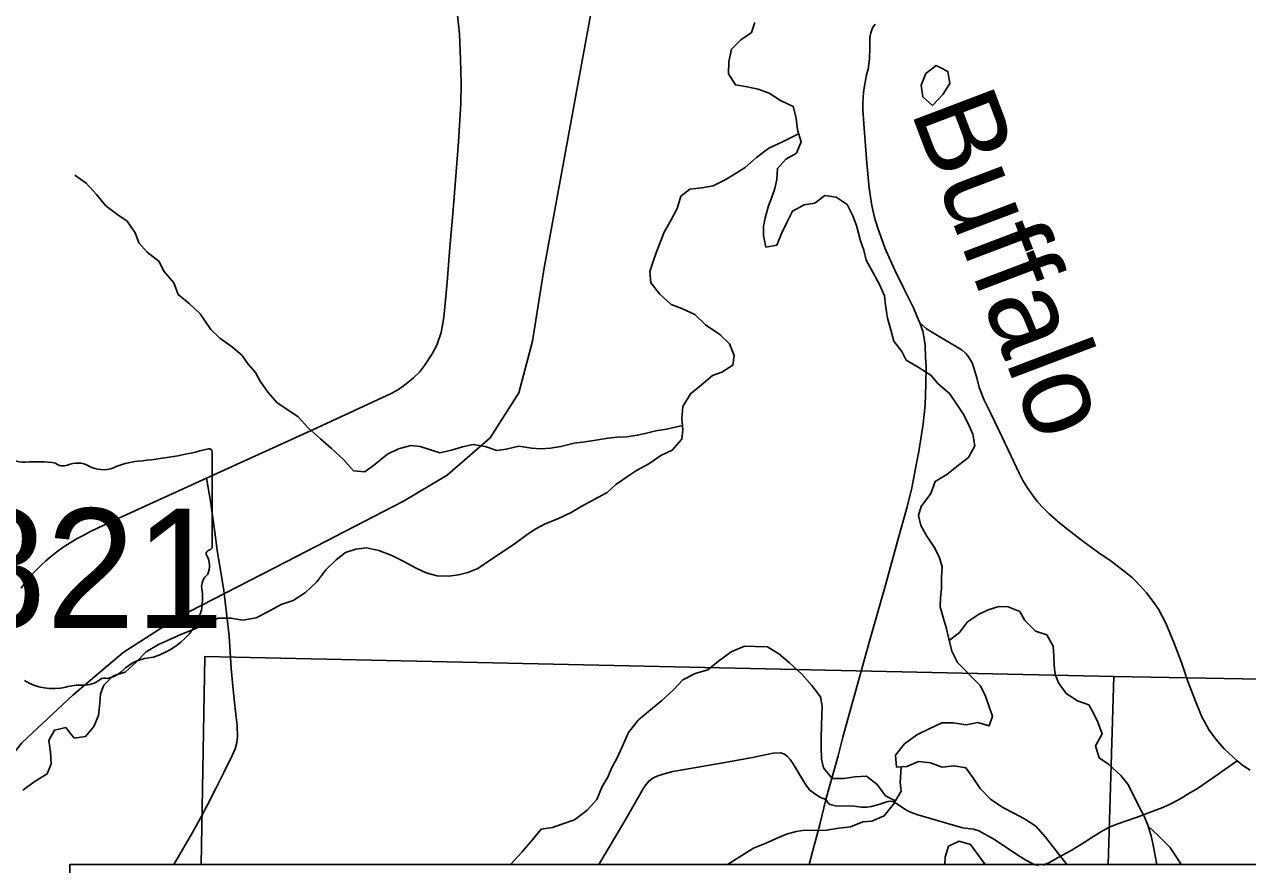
# Model space of a CAD drawing. Extents: x 0 to 34, y 0 to 22.
# Drawn here: x 5.615 to 6.964, y 18.86 to 19.787 of the extents above; entities that cross this region are included whole.
import ezdxf

# ---------------------------------------------------------------- set-up
doc = ezdxf.new("R2010")
doc.units = 0
for name, color, linetype in [('GM_X_Corporation', 7, 'Continuous'), ('GM_X_County_Road', 7, 'Continuous'), ('GM_X_Minor_Lake', 7, 'Continuous'), ('GM_X_Minor_River', 7, 'Continuous'), ('GM_X_Minor_River_Text', 7, 'Continuous'), ('GM_X_Rail_Line', 7, 'Continuous'), ('GM_X_State_Location', 7, 'Continuous'), ('GM_X_State_Route', 7, 'Continuous'), ('GM_X_State_Shield', 7, 'Continuous'), ('GM_X_Township_Road', 7, 'Continuous'), ('SH_Data', 7, 'Continuous')]:
    doc.layers.add(name, color=color, linetype=linetype)

msp = doc.modelspace()

# ---------------------------------------------------------------- linework, layer by layer
at = {"layer": 'GM_X_Corporation'}
for points in [[(5.8098, 18.8602), (5.814, 19.0894), (6.8161, 19.0676), (6.8097, 18.8602)], [(6.8097, 18.8602), (6.8161, 19.0676), (7.8304, 19.049), (7.8278, 18.8602)]]:
    msp.add_lwpolyline(points, dxfattribs=at)
at = {"layer": 'GM_X_County_Road'}
for points in [[(6.6022, 19.4574), (6.6096, 19.4508), (6.6197, 19.4445), (6.6333, 19.4366), (6.6416, 19.4317), (6.6487, 19.4273), (6.6525, 19.4242), (6.655, 19.4212), (6.6599, 19.4133), (6.6619, 19.408), (6.6651, 19.3969), (6.6676, 19.3864), (6.6731, 19.3724), (6.6806, 19.3576), (6.6933, 19.3307), (6.7057, 19.3043), (6.7116, 19.2917), (6.7157, 19.2835), (6.7206, 19.276), (6.7267, 19.2672), (6.7321, 19.2601), (6.7384, 19.2533), (6.7449, 19.2468), (6.7569, 19.2364), (6.7685, 19.227), (6.7834, 19.2155), (6.8023, 19.2022), (6.8118, 19.1957), (6.8214, 19.1885), (6.8293, 19.1822), (6.8366, 19.1762), (6.8456, 19.1673), (6.8522, 19.1597), (6.8591, 19.1505), (6.8654, 19.1416), (6.8734, 19.1263), (6.8824, 19.1049), (6.8908, 19.083), (6.8974, 19.0631), (6.906, 19.0402), (6.9131, 19.0231), (6.9212, 19.0084), (6.9287, 18.9984), (6.9376, 18.9878), (6.9521, 18.9744), (6.9585, 18.9695), (6.9663, 18.9641)], [(5.7797, 18.8602), (5.8004, 18.8954), (5.8098, 18.9127), (5.8168, 18.9259), (5.8263, 18.9448), (5.8343, 18.9611), (5.8442, 18.9805), (5.8475, 18.9878), (5.849, 18.9948), (5.85, 19.0009), (5.8495, 19.0136), (5.8473, 19.0323), (5.8453, 19.0532), (5.8431, 19.0765), (5.8407, 19.1122), (5.8347, 19.1624), (5.8276, 19.2069), (5.8248, 19.2267), (5.82, 19.2607), (5.8159, 19.2861)]]:
    msp.add_lwpolyline(points, dxfattribs=at)
at = {"layer": 'GM_X_Minor_Lake'}
for points in [[(6.6252, 19.7387), (6.6201, 19.7413), (6.6087, 19.7326), (6.6038, 19.7197), (6.6056, 19.7068), (6.6162, 19.6973)], [(6.6162, 19.6973), (6.6276, 19.7094), (6.6352, 19.7215), (6.6329, 19.7348), (6.6252, 19.7387)]]:
    msp.add_lwpolyline(points, dxfattribs=at)
at = {"layer": 'GM_X_Minor_River'}
for points in [[(6.4201, 19.7889), (6.4167, 19.7776), (6.405, 19.7696), (6.3947, 19.7594), (6.3917, 19.7457), (6.3913, 19.7321), (6.3988, 19.72), (6.4117, 19.7177), (6.4241, 19.7154), (6.4362, 19.7108), (6.4487, 19.7028), (6.4627, 19.696), (6.4657, 19.6831), (6.4672, 19.6702), (6.4713, 19.6573), (6.4664, 19.6448), (6.4546, 19.638), (6.4452, 19.6278), (6.4444, 19.6157), (6.4425, 19.6058), (6.439, 19.596), (6.4352, 19.5865), (6.4318, 19.5732), (6.4299, 19.5638), (6.4299, 19.5539), (6.4325, 19.541), (6.4446, 19.5433), (6.4496, 19.5562), (6.4556, 19.5683), (6.4617, 19.5808), (6.4746, 19.5876), (6.4863, 19.5895), (6.4973, 19.5978), (6.5098, 19.5962), (6.5222, 19.5879), (6.5282, 19.5754), (6.5324, 19.5648), (6.5369, 19.5481), (6.5403, 19.5378), (6.5429, 19.5268), (6.5508, 19.5128), (6.5576, 19.4999), (6.5632, 19.4874), (6.5644, 19.4772), (6.5666, 19.4628), (6.5704, 19.4499), (6.5737, 19.4373), (6.5824, 19.426), (6.5873, 19.4165), (6.6005, 19.4085), (6.6145, 19.3998), (6.6224, 19.3903), (6.6349, 19.3796), (6.6428, 19.3683), (6.6507, 19.3561), (6.6564, 19.3447), (6.6605, 19.3349), (6.6628, 19.322), (6.6559, 19.3091), (6.6449, 19.3004), (6.6321, 19.2902), (6.6192, 19.2826), (6.6143, 19.2694), (6.6036, 19.255), (6.6006, 19.2451), (6.6032, 19.2341), (6.61, 19.2224), (6.6187, 19.2091), (6.624, 19.1985), (6.627, 19.1886), (6.6262, 19.1773), (6.6262, 19.1644), (6.625, 19.1541), (6.6246, 19.1443)], [(6.4685, 19.666), (6.4501, 19.6566), (6.4357, 19.6502), (6.4221, 19.64), (6.4096, 19.629), (6.3998, 19.6226), (6.3876, 19.6154), (6.3744, 19.6086), (6.3619, 19.6063), (6.3487, 19.6048), (6.3388, 19.5972), (6.3346, 19.5836), (6.3282, 19.5711), (6.3202, 19.5575), (6.3168, 19.548), (6.3119, 19.5359), (6.3081, 19.5253), (6.3046, 19.5143), (6.3058, 19.5018), (6.3156, 19.4892), (6.328, 19.4779), (6.3397, 19.4733), (6.3541, 19.4668), (6.3658, 19.4554), (6.3817, 19.4448), (6.3922, 19.4342), (6.3975, 19.4217), (6.396, 19.4107), (6.3838, 19.4031), (6.3736, 19.3993), (6.3615, 19.3891), (6.3494, 19.3793), (6.341, 19.3653), (6.3399, 19.352), (6.341, 19.3395), (6.3398, 19.3293), (6.3292, 19.3171), (6.3167, 19.3111), (6.3035, 19.302), (6.2899, 19.2948), (6.28, 19.288), (6.2671, 19.2793), (6.2573, 19.2706), (6.2433, 19.2627), (6.2297, 19.2555), (6.2179, 19.2483), (6.2032, 19.2415), (6.1892, 19.2358), (6.1789, 19.2305), (6.1691, 19.2241), (6.1551, 19.2135), (6.129, 19.1961), (6.1149, 19.1866), (6.104, 19.1821), (6.0934, 19.1795), (6.0828, 19.178), (6.0699, 19.1784), (6.0578, 19.1818), (6.0469, 19.1871), (6.0333, 19.1943), (6.0201, 19.2008), (6.0057, 19.2065), (5.9921, 19.2095), (5.9804, 19.208), (5.969, 19.2043), (5.9588, 19.1963), (5.9474, 19.1853), (5.9372, 19.1721), (5.9247, 19.16), (5.9114, 19.1513), (5.8982, 19.1471), (5.8834, 19.1388), (5.8706, 19.1324), (5.8558, 19.1297), (5.8426, 19.132), (5.8286, 19.132), (5.8157, 19.126), (5.8021, 19.1196), (5.7881, 19.1143), (5.776, 19.1086), (5.7627, 19.1029), (5.7491, 19.0946), (5.7381, 19.0833), (5.726, 19.0723), (5.7128, 19.0681), (5.7025, 19.0579), (5.6987, 19.0484), (5.698, 19.0382), (5.6968, 19.0245), (5.6915, 19.0124), (5.6824, 19.0014), (5.6699, 18.9996), (5.6605, 19.0113), (5.648, 19.0083), (5.6419, 18.9969), (5.6438, 18.9841), (5.6445, 18.9712), (5.64, 18.9602), (5.6267, 18.9522), (5.6134, 18.942)], [(6.3406, 19.3442), (6.3228, 19.3403), (6.3111, 19.3384), (6.3009, 19.3357), (6.2907, 19.3335), (6.2793, 19.332), (6.2691, 19.3316), (6.2585, 19.3305), (6.2449, 19.3282), (6.2332, 19.3264), (6.2211, 19.3249), (6.2063, 19.3211), (6.195, 19.3192), (6.1848, 19.3185), (6.1742, 19.3192), (6.1602, 19.3215), (6.1462, 19.3181), (6.136, 19.3166), (6.1231, 19.3212), (6.1099, 19.3235), (6.0978, 19.3208), (6.0857, 19.3171), (6.0728, 19.3141), (6.0513, 19.3213), (6.0411, 19.3221), (6.0275, 19.3187), (6.0154, 19.3126), (6.0017, 19.3016), (5.9904, 19.2933), (5.9779, 19.2945), (5.9669, 19.307), (5.9537, 19.3191), (5.9413, 19.3298), (5.9281, 19.3415), (5.9167, 19.3537), (5.9065, 19.3609), (5.8937, 19.3692), (5.8835, 19.381), (5.8748, 19.3931), (5.8696, 19.4026), (5.8616, 19.4121), (5.8549, 19.4216), (5.8443, 19.4307), (5.8303, 19.4406), (5.8205, 19.4501), (5.8088, 19.4675), (5.7967, 19.4789), (5.7846, 19.4888), (5.7798, 19.5017), (5.7688, 19.5146), (5.7635, 19.5252), (5.7503, 19.5354), (5.7413, 19.5457), (5.7371, 19.5567), (5.7281, 19.5696), (5.7179, 19.5768), (5.7047, 19.5867), (5.6945, 19.5992), (5.6832, 19.6117), (5.6707, 19.6204)], [(6.6246, 19.1443), (6.6284, 19.1314), (6.6314, 19.1215), (6.634, 19.109), (6.6374, 19.0954), (6.6438, 19.0828), (6.6691, 19.0574), (6.6747, 19.0457), (6.6788, 19.0339), (6.6822, 19.0237), (6.6788, 19.0131), (6.666, 19.0169), (6.6531, 19.0142), (6.6391, 19.0165), (6.6266, 19.0165), (6.6126, 19.0097), (6.599, 19.0033), (6.5854, 18.9931), (6.5755, 18.9806), (6.5766, 18.9677), (6.588, 18.9681), (6.6008, 18.9737), (6.6141, 18.9722), (6.6269, 18.9676), (6.6402, 18.9691), (6.653, 18.9668), (6.6605, 18.9562), (6.6688, 18.9441), (6.6802, 18.9323), (6.6938, 18.9232), (6.7059, 18.9167), (6.7176, 18.9107), (6.73, 18.9023), (6.7406, 18.8905), (6.7642, 18.8602)], [(6.6344, 19.1072), (6.6461, 19.1162), (6.6548, 19.1279), (6.6669, 19.1359), (6.6775, 19.1412), (6.6893, 19.1449), (6.6995, 19.1442), (6.7123, 19.1392), (6.718, 19.1294), (6.7297, 19.1176), (6.7421, 19.1134), (6.7493, 19.1009), (6.75, 19.0899), (6.7504, 19.0797), (6.7515, 19.0702), (6.7549, 19.0607), (6.7636, 19.0486), (6.776, 19.0406), (6.7885, 19.0364), (6.7942, 19.0265), (6.7983, 19.0171), (6.8032, 19.0042), (6.796, 18.9909), (6.8001, 18.978), (6.8103, 18.9708), (6.8239, 18.9583), (6.8315, 18.9488), (6.839, 18.9344), (6.8439, 18.9238), (6.8492, 18.9143), (6.8533, 18.9048), (6.8571, 18.8919), (6.8593, 18.8817), (6.8636, 18.8602)], [(6.5752, 18.9304), (6.5645, 18.9359), (6.555, 18.9484), (6.5433, 18.9575), (6.5305, 18.9568), (6.5187, 18.9549), (6.5055, 18.9549), (6.4961, 18.9667), (6.4938, 18.9762), (6.4935, 18.9898), (6.4935, 19), (6.4939, 19.0126), (6.4943, 19.0254), (6.4947, 19.0349), (6.4928, 19.0451), (6.483, 19.0577), (6.4721, 19.0702), (6.4585, 19.0827), (6.4468, 19.0926), (6.4343, 19.1002), (6.4207, 19.1006), (6.409, 19.101), (6.3942, 19.0949), (6.3802, 19.0843), (6.3685, 19.0749), (6.3545, 19.0707), (6.3408, 19.0639), (6.331, 19.0533), (6.3177, 19.0412), (6.3052, 19.0306), (6.2916, 19.0193), (6.281, 19.0056), (6.2741, 18.9901), (6.2684, 18.978), (6.2624, 18.9666), (6.2582, 18.9564), (6.2521, 18.9462), (6.2461, 18.9318), (6.2354, 18.92), (6.2214, 18.9094), (6.2074, 18.9045), (6.1972, 18.9011), (6.1847, 18.8992), (6.1749, 18.8871), (6.1635, 18.8739), (6.1508, 18.8602)], [(6.5818, 18.9679), (6.5804, 18.9506), (6.5815, 18.9412), (6.5731, 18.9268), (6.5629, 18.9139), (6.5493, 18.9079), (6.5394, 18.9071), (6.5258, 18.9018), (6.513, 18.9003), (6.4993, 18.8981), (6.4854, 18.8977), (6.4755, 18.8981), (6.4657, 18.8966), (6.4551, 18.8936), (6.4422, 18.8883), (6.4316, 18.8834), (6.4188, 18.8781), (6.3902, 18.8602)], [(6.8539, 18.9026), (6.8654, 18.8919), (6.8778, 18.8794), (6.8861, 18.8672), (6.8902, 18.8602)], [(6.6743, 18.8602), (6.6581, 18.8823), (6.6457, 18.8861), (6.6339, 18.8805), (6.6301, 18.8683), (6.6298, 18.8602)]]:
    msp.add_lwpolyline(points, dxfattribs=at)
at = {"layer": 'GM_X_Rail_Line'}
msp.add_lwpolyline([(5.1451, 18.1171), (5.1789, 18.1962), (5.2191, 18.2747), (5.3419, 18.505), (5.4365, 18.6966), (5.5699, 18.941), (5.612, 18.9944), (5.6684, 19.0468), (5.7239, 19.094), (5.7833, 19.1322), (5.9037, 19.1938), (6.0328, 19.261), (6.0812, 19.2894), (6.1283, 19.3307), (6.1601, 19.3803), (6.1751, 19.4374), (6.1878, 19.5161), (6.2911, 20.0794)], dxfattribs=at)
at = {"layer": 'GM_X_State_Route'}
for points in [[(5.6113, 19.1649), (5.6154, 19.1703), (5.6218, 19.178), (5.6279, 19.1848), (5.6337, 19.1906), (5.6385, 19.195), (5.6435, 19.1993), (5.6506, 19.2049), (5.6576, 19.2101), (5.6733, 19.2196), (5.6804, 19.2234), (5.6871, 19.227), (5.7108, 19.2384), (5.8159, 19.2861), (5.9385, 19.3422), (6.0193, 19.3795), (6.0275, 19.384), (6.036, 19.3903), (6.044, 19.3968), (6.0505, 19.4033), (6.056, 19.4106), (6.0645, 19.4235), (6.0695, 19.433), (6.0745, 19.4467), (6.0773, 19.4634), (6.0812, 19.5023), (6.0841, 19.5407), (6.0872, 19.5779), (6.0906, 19.6191), (6.0934, 19.6571), (6.0962, 19.6994), (6.0966, 19.7215), (6.0959, 19.748), (6.0945, 19.7761), (6.092, 19.8004)], [(6.5528, 19.7868), (6.5501, 19.7827), (6.548, 19.7775), (6.5471, 19.7724), (6.5471, 19.7613), (6.5468, 19.7488), (6.5451, 19.7373), (6.5435, 19.7309), (6.5411, 19.7189), (6.5402, 19.7115), (6.5392, 19.6997), (6.5394, 19.6931), (6.5405, 19.677), (6.5436, 19.6338), (6.5463, 19.606), (6.5493, 19.5871), (6.5523, 19.5737), (6.5555, 19.5631), (6.5635, 19.5401), (6.5748, 19.5155), (6.5843, 19.4962), (6.5951, 19.474), (6.5994, 19.4642), (6.6022, 19.4574), (6.6054, 19.4484), (6.6066, 19.4426), (6.6079, 19.4324), (6.6085, 19.4195), (6.609, 19.4091), (6.6088, 19.3898), (6.6081, 19.3669), (6.606, 19.3462), (6.6014, 19.3179), (6.601, 19.3158)], [(6.601, 19.3158), (6.5988, 19.3046), (6.5933, 19.2757), (6.5882, 19.2547), (6.5784, 19.2193), (6.5643, 19.1682), (6.5466, 19.1066), (6.5301, 19.0471), (6.5239, 19.0244), (6.5172, 19.0005), (6.512, 18.9799), (6.4987, 18.9317), (6.492, 18.9044), (6.4844, 18.8756), (6.4802, 18.8602)]]:
    msp.add_lwpolyline(points, dxfattribs=at)
at = {"layer": 'GM_X_State_Shield'}
for q in [(5.8219, 19.3153), (5.8219, 19.2106)]:
    msp.add_line((5.8219, 19.2106), q, dxfattribs=at)
for centre, major_axis, start_param, end_param in [((5.6151, 19.3336), (0.037, 0), 4.042523, 4.731795), ((5.7045, 19.5832), (0.3495, 0), 4.814394, 5.042369), ((5.8183, 19.3157), (0.00367, 0), 6.141152, 7.989035), ((5.6274, 19.198), (0.133, 0), 1.404758, 1.657858), ((5.6576, 19.3083), (0.0107, 0), 3.836095, 5.185415), ((5.6733, 19.2852), (0.0222, 0), 0.950623, 2.079405), ((5.7019, 19.3169), (0.0267, 0), 4.081561, 5.145723), ((5.7491, 19.2492), (0.0703, 0), 1.699011, 2.107814), ((5.8211, 19.2029), (0.00568, 0), 1.883978, 3.671073), ((5.818, 19.2102), (0.00393, 0), 5.05454, 6.418171), ((5.785, 19.1897), (0.0341, 0), 5.934695, 6.695948), ((5.8351, 19.1668), (0.0248, 0), 2.387724, 3.262537), ((5.7241, 19.1535), (0.0874, 0), 5.101752, 6.440018), ((5.761, 19.0506), (0.0479, 0), 1.647645, 2.488434), ((5.7003, 19.0874), (0.0282, 0), 4.937069, 5.64225), ((5.6468, 19.0942), (0.0501, 0), 4.026481, 4.996735), ((5.6757, 19.025), (0.0412, 0), 1.495662, 1.94098), ((5.6794, 19.0792), (0.0267, 0), 4.691044, 5.507374), ((5.7035, 19.0599), (0.00752, 0), 1.147584, 2.315152)]:
    msp.add_ellipse(centre, major_axis=major_axis, ratio=0.8, start_param=start_param, end_param=end_param, dxfattribs=at)
at = {"layer": 'GM_X_Township_Road'}
for points in [[(6.2483, 18.8602), (6.277, 18.9083), (6.2977, 18.9442), (6.3002, 18.9481), (6.3033, 18.9522), (6.3077, 18.9553), (6.3132, 18.9578), (6.318, 18.9596), (6.3229, 18.961), (6.3298, 18.9627), (6.3386, 18.9643), (6.3851, 18.9722), (6.4157, 18.9777), (6.4405, 18.983), (6.4488, 18.9832), (6.4529, 18.9817), (6.4564, 18.9792), (6.4592, 18.9759), (6.4625, 18.9711), (6.475, 18.9504), (6.4782, 18.9455), (6.4809, 18.942), (6.4864, 18.9381), (6.4926, 18.9342), (6.4987, 18.9317)], [(6.7379, 18.8595), (6.7445, 18.862), (6.7541, 18.8677), (6.7689, 18.8756), (6.7832, 18.8843), (6.794, 18.8916), (6.8042, 18.8976), (6.8121, 18.9017), (6.8206, 18.9051), (6.8419, 18.9123), (6.8553, 18.9175), (6.8702, 18.9231), (6.8796, 18.9275), (6.8898, 18.933), (6.8987, 18.9385), (6.9085, 18.9441), (6.9249, 18.9555), (6.9521, 18.9744)], [(6.4987, 18.9317), (6.501, 18.9279), (6.5033, 18.9264), (6.5093, 18.9249), (6.5297, 18.9245), (6.5379, 18.9236), (6.5442, 18.9235), (6.5489, 18.9242), (6.557, 18.9265), (6.567, 18.9296), (6.5699, 18.9301), (6.5725, 18.9297), (6.5763, 18.9276), (6.5847, 18.9218), (6.5882, 18.9198), (6.592, 18.918), (6.5999, 18.915), (6.6493, 18.9006), (6.6613, 18.899), (6.6673, 18.8974), (6.6845, 18.8879), (6.7104, 18.8706), (6.7192, 18.8651), (6.7281, 18.8602), (6.7331, 18.859)]]:
    msp.add_lwpolyline(points, dxfattribs=at)
at = {"layer": 'SH_Data'}
msp.add_lwpolyline([(5.6652, 18.0831), (8.1124, 18.0831), (8.1124, 18.8602), (5.6652, 18.8602)], close=True, dxfattribs=at)

# ---------------------------------------------------------------- texts
at = {"layer": 'GM_X_Minor_River_Text'}
msp.add_text('Buffalo', height=0.09468, rotation=290.7843, dxfattribs=at).set_placement((6.5916, 19.6912))
at = {"layer": 'GM_X_State_Location'}
for s, p in [('s', (5.6535, 19.1935)), ('r', (5.6534, 19.1935))]:
    msp.add_text(s, height=0.000189, dxfattribs=at).set_placement(p)
at = {"layer": 'GM_X_State_Shield'}
msp.add_text('821', height=0.13184, dxfattribs=at).set_placement((5.5409, 19.1209))

doc.saveas('drawing.dxf')
